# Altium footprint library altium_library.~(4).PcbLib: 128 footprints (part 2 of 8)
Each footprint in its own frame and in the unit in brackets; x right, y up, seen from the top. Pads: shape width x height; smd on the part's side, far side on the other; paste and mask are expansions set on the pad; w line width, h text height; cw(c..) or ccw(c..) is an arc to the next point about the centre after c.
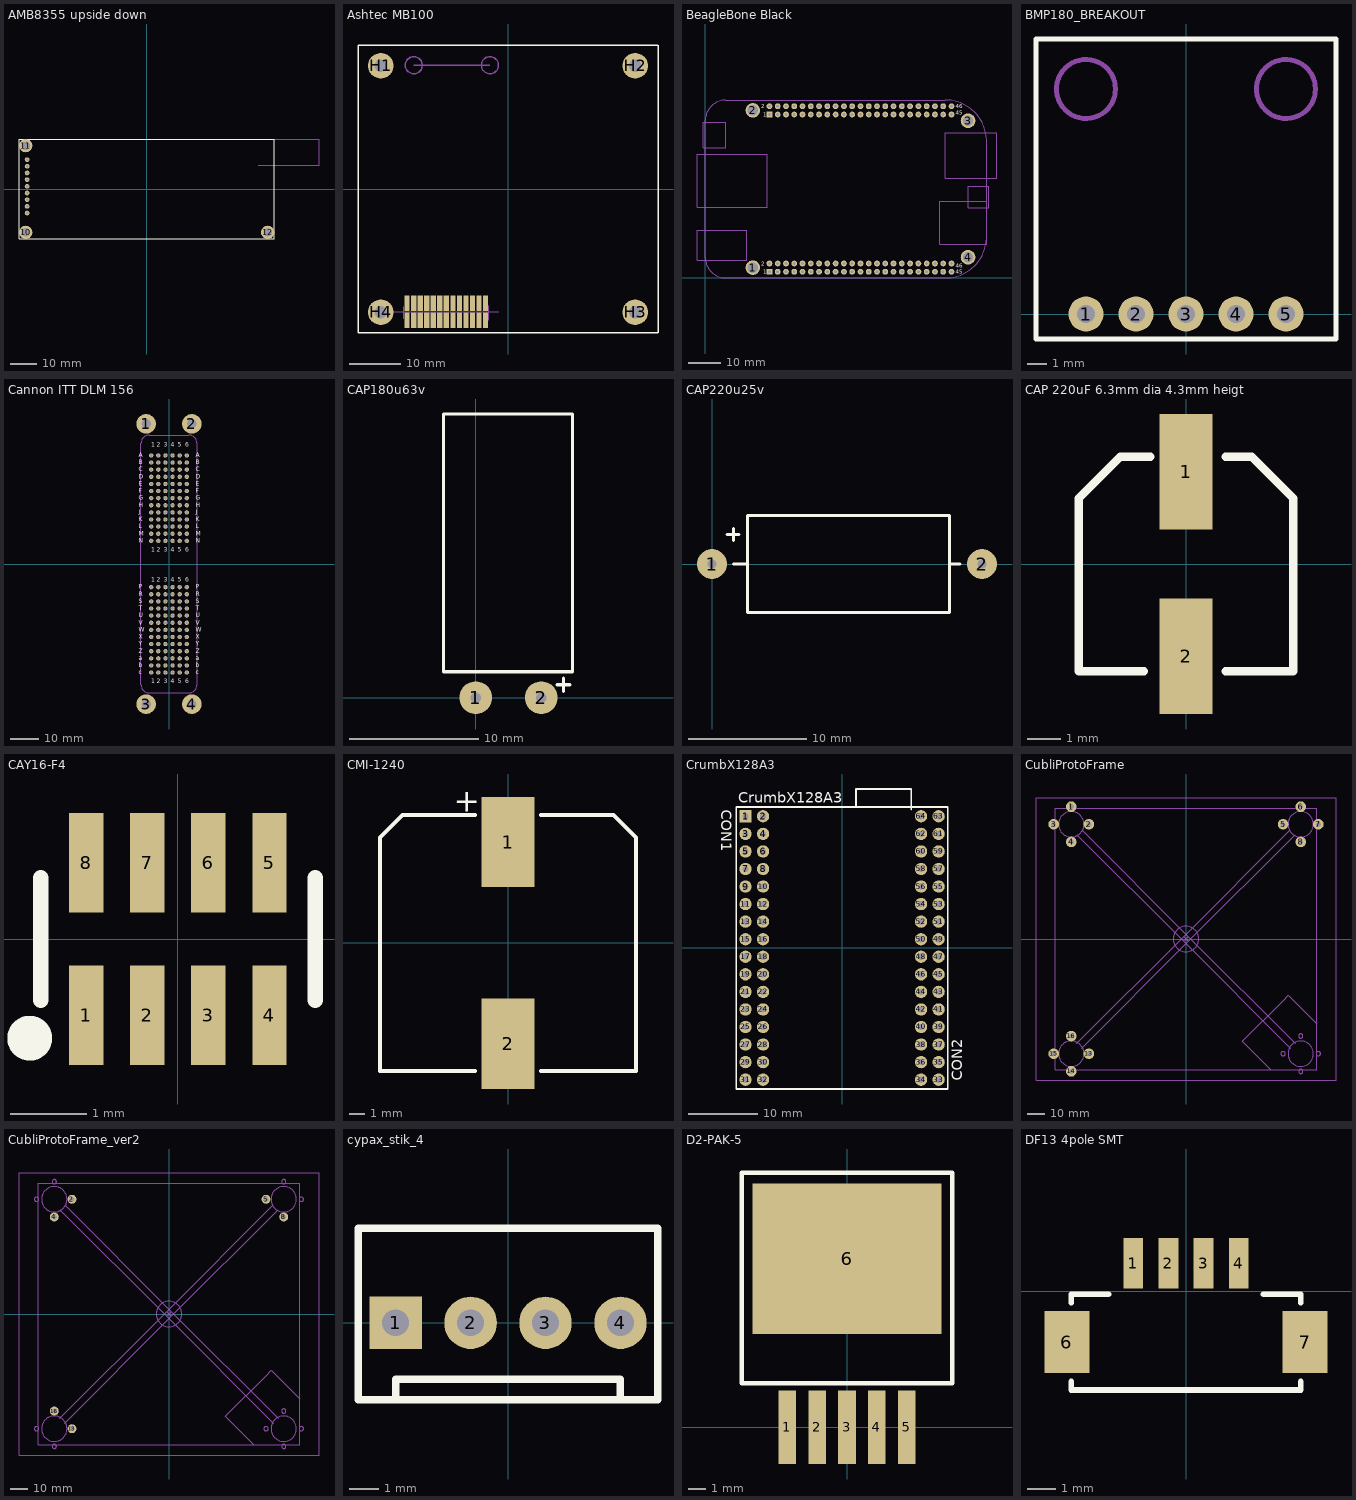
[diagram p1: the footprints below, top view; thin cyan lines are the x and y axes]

## AMB8355 upside down [mil] "Amber Wireless 868Mhz -- RTK GPS"
pads (12):
  round 70 hole 35.43: 1(-1790.16,440) 2(-1790.16,340) 3(-1790.16,240) 4(-1790.16,140) 5(-1790.16,40) 6(-1790.16,-60) 7(-1790.16,-160) 8(-1790.16,-260) 9(-1790.16,-360)
  round 200 hole 125.98: 10(-1811.02,-649.61) 11(-1811.02,649.61) 12(1811.02,-649.61)
Top Overlay:
  lines w10: -1909.45,-748.03 -1909.45,748.03 1909.45,748.03 1909.45,-748.03 -1909.45,-748.03
Mechanical 1:
  lines w10: 1673.23,354.33 2578.74,354.33 2578.74,748.03 1909.45,748.03

## Ashtec MB100 [mm] "RTK GPS reciever"
pads (30):
  rect 1x3 smd: 1(-19.634,-22.225) 2(-19.634,-25.578) 3(-18.364,-22.225) 4(-18.364,-25.578) 5(-17.094,-22.225) 6(-17.094,-25.578) 7(-15.824,-22.225) 8(-15.824,-25.578) 9(-14.554,-22.225) 10(-14.554,-25.578) 11(-13.284,-22.225) 12(-13.284,-25.578) 13(-12.014,-22.225) 14(-12.014,-25.578) 15(-10.744,-22.225) 16(-10.744,-25.578) 17(-9.474,-22.225) 18(-9.474,-25.578) 19(-8.204,-22.225) 20(-8.204,-25.578) 21(-6.934,-22.225) 22(-6.934,-25.578) 23(-5.664,-22.225) 24(-5.664,-25.578) 25(-4.394,-22.225) 26(-4.394,-25.578)
  round 5 hole 2.4: H1(-24.765,24) H2(24.765,24) H3(24.765,-24) H4(-24.765,-24)
Top Overlay:
  lines w0.254: -29.21,-28 -29.21,28 ; -29.2,-28 29.2,-28 ; -29.2,28 29.2,28 ; 29.21,-28 29.21,28
Mechanical 1:
  circle w0.254: c-3.52,24.1 r1.663
  circle w0.254: c-18.37,24.1 r1.663
  lines w0.025: -24.765,-23.9 -1.8,-23.9 ; -20.26,-25.298 -20.26,-22.898 ; -3.76,-25.598 -3.76,-22.698
  lines w0.254: -18.37,24.1 -3.52,24.1

## BeagleBone Black [mil]
pads (96):
  round 177.16 hole 125.98: 1(575,125) 2(575,2025) 3(3175,1900) 4(3175,250)
  rect 70x70 hole 35.43: P8-1(775,1975) P9-1(775,75)
  round 70 hole 35.43: P8-2(775,2075) P8-3(875,1975) P8-4(875,2075) P8-5(975,1975) P8-6(975,2075) P8-7(1075,1975) P8-8(1075,2075) P8-9(1175,1975) P8-10(1175,2075) P8-11(1275,1975) P8-12(1275,2075) P8-13(1375,1975) P8-14(1375,2075) P8-15(1475,1975) P8-16(1475,2075) P8-17(1575,1975) P8-18(1575,2075) P8-19(1675,1975) P8-20(1675,2075) P8-21(1775,1975) P8-22(1775,2075) P8-23(1875,1975) P8-24(1875,2075) P8-25(1975,1975) P8-26(1975,2075) P8-27(2075,1975) P8-28(2075,2075) P8-29(2175,1975) P8-30(2175,2075) P8-31(2275,1975) P8-32(2275,2075) P8-33(2375,1975) P8-34(2375,2075) P8-35(2475,1975) P8-36(2475,2075) P8-37(2575,1975) P8-38(2575,2075) P8-39(2675,1975) P8-40(2675,2075) P8-41(2775,1975) P8-42(2775,2075) P8-43(2875,1975) P8-44(2875,2075) P8-45(2975,1975) P8-46(2975,2075) P9-2(775,175) P9-3(875,75) P9-4(875,175) P9-5(975,75) P9-6(975,175) P9-7(1075,75) P9-8(1075,175) P9-9(1175,75) P9-10(1175,175) P9-11(1275,75) P9-12(1275,175) P9-13(1375,75) P9-14(1375,175) P9-15(1475,75) P9-16(1475,175) P9-17(1575,75) P9-18(1575,175) P9-19(1675,75) P9-20(1675,175) P9-21(1775,75) P9-22(1775,175) P9-23(1875,75) P9-24(1875,175) P9-25(1975,75) P9-26(1975,175) P9-27(2075,75) P9-28(2075,175) P9-29(2175,75) P9-30(2175,175) P9-31(2275,75) P9-32(2275,175) P9-33(2375,75) P9-34(2375,175) P9-35(2475,75) P9-36(2475,175) P9-37(2575,75) P9-38(2575,175) P9-39(2675,75) P9-40(2675,175) P9-41(2775,75) P9-42(2775,175) P9-43(2875,75) P9-44(2875,175) P9-45(2975,75) P9-46(2975,175)
Top Overlay:
  text "1" at 700,1950 h50
  text "2" at 675,2050 h50
  text "45" at 3025,1975 h50
  text "46" at 3025,2050 h50
  text "46" at 3025,125 h50
  text "45" at 3025,50 h50
  text "2" at 675,150 h50
  text "1" at 700,50 h50
Bottom Overlay:
  text "1" at 700,1950 h50
  text "2" at 725,2050 h50
  text "45" at 3125,1975 h50
  text "46" at 3125,2050 h50
  text "46" at 3125,125 h50
  text "45" at 3125,50 h50
  text "2" at 725,150 h50
  text "1" at 700,50 h50
Mechanical 1:
  lines w10: 0,250 ccw(c250,250) 250,0 2900,0 ccw(c2900,500) 3400,500 3400,1650 ccw(c2900,1650) 2900,2150 250,2150 ccw(c250,1900) 0,1900 0,250
Mechanical 2:
  lines w10: -100,215 500,215 500,575 -100,575 -100,215 ; -100,855 750,855 750,1495 -100,1495 -100,855 ; -25,1575 250,1575 250,1880 -25,1880 -25,1575 ; 2834.65,405 2834.65,925 3400,925 3400,405 2834.65,405 ; 2900,1205 2900,1755 3525,1755 3525,1205 2900,1205 ; 3175,850 3425,850 3425,1110 3175,1110 3175,850

## BMP180_BREAKOUT [mil]
pads (5):
  round 70 hole 35.43: 1(-200,0) 2(-100,0) 3(0,0) 4(100,0) 5(200,0)
Top Overlay:
  lines w10: -300,-50 300,-50 300,550 -300,550 -300,-50
Mechanical 1:
  circle w10: c200,450 r59.06
  circle w10: c-200,450 r59.06

## Cannon ITT DLM 156 [mil] "Cannon ITT ZIF DLM 156 pin Connector"
pads (160):
  round 275.59 hole 129.92: 1(-320.08,1968.9) 2(320.08,1968.9) 3(-320.08,-1968.9) 4(320.08,-1968.9)
  round 60 hole 39.37: A1(-250,1525) A2(-150,1525) A3(-50,1525) A4(50,1525) A5(150,1525) A6(250,1525) a¤1(-250,-1325) a¤2(-150,-1325) a¤3(-50,-1325) a¤4(50,-1325) a¤5(150,-1325) a¤6(250,-1325) B1(-250,1425) B2(-150,1425) B3(-50,1425) B4(50,1425) B5(150,1425) B6(250,1425) b¤1(-250,-1425) b¤2(-150,-1425) b¤3(-50,-1425) b¤4(50,-1425) b¤5(150,-1425) b¤6(250,-1425) C1(-250,1325) C2(-150,1325) C3(-50,1325) C4(50,1325) C5(150,1325) C6(250,1325) c¤1(-250,-1525) c¤2(-150,-1525) c¤3(-50,-1525) c¤4(50,-1525) c¤5(150,-1525) c¤6(250,-1525) D1(-250,1225) D2(-150,1225) D3(-50,1225) D4(50,1225) D5(150,1225) D6(250,1225) E1(-250,1125) E2(-150,1125) E3(-50,1125) E4(50,1125) E5(150,1125) E6(250,1125) F1(-250,1025) F2(-150,1025) F3(-50,1025) F4(50,1025) F5(150,1025) F6(250,1025) G1(-250,925) G2(-150,925) G3(-50,925) G4(50,925) G5(150,925) G6(250,925) H1(-250,825) H2(-150,825) H3(-50,825) H4(50,825) H5(150,825) H6(250,825) J1(-250,725) J2(-150,725) J3(-50,725) J4(50,725) J5(150,725) J6(250,725) K1(-250,625) K2(-150,625) K3(-50,625) K4(50,625) K5(150,625) K6(250,625) L1(-250,525) L2(-150,525) L3(-50,525) L4(50,525) L5(150,525) L6(250,525) M1(-250,425) M2(-150,425) M3(-50,425) M4(50,425) M5(150,425) M6(250,425) N1(-250,325) N2(-150,325) N3(-50,325) N4(50,325) N5(150,325) N6(250,325) P1(-250,-325) P2(-150,-325) P3(-50,-325) P4(50,-325) P5(150,-325) P6(250,-325) R1(-250,-425) R2(-150,-425) R3(-50,-425) R4(50,-425) R5(150,-425) R6(250,-425) S1(-250,-525) S2(-150,-525) S3(-50,-525) S4(50,-525) S5(150,-525) S6(250,-525) T1(-250,-625) T2(-150,-625) T3(-50,-625) T4(50,-625) T5(150,-625) T6(250,-625) U1(-250,-725) U2(-150,-725) U3(-50,-725) U4(50,-725) U5(150,-725) U6(250,-725) V1(-250,-825) V2(-150,-825) V3(-50,-825) V4(50,-825) V5(150,-825) V6(250,-825) W1(-250,-925) W2(-150,-925) W3(-50,-925) W4(50,-925) W5(150,-925) W6(250,-925) X1(-250,-1025) X2(-150,-1025) X3(-50,-1025) X4(50,-1025) X5(150,-1025) X6(250,-1025) Y1(-250,-1125) Y2(-150,-1125) Y3(-50,-1125) Y4(50,-1125) Y5(150,-1125) Y6(250,-1125) Z1(-250,-1225) Z2(-150,-1225) Z3(-50,-1225) Z4(50,-1225) Z5(150,-1225) Z6(250,-1225)
Top Overlay:
  text "1" at -250,-1675 h60
  text "2" at -175,-1675 h60
  text "3" at -75,-1675 h60
  text "4" at 25,-1675 h60
  text "5" at 125,-1675 h60
  text "6" at 225,-1675 h60
  text "1" at -250,-250 h60
  text "2" at -175,-250 h60
  text "3" at -75,-250 h60
  text "4" at 25,-250 h60
  text "5" at 125,-250 h60
  text "6" at 225,-250 h60
  text "1" at -250,175 h60
  text "2" at -175,175 h60
  text "3" at -75,175 h60
  text "4" at 25,175 h60
  text "5" at 125,175 h60
  text "6" at 225,175 h60
  text "6" at 225,1650 h60
  text "5" at 125,1650 h60
  text "4" at 25,1650 h60
  text "3" at -75,1650 h60
  text "2" at -175,1650 h60
  text "1" at -250,1650 h60
  text "A" at 375,1500 h60
  text "B" at 375,1400 h60
  text "C" at 375,1300 h60
  text "D" at 375,1200 h60
  text "E" at 375,1100 h60
  text "F" at 375,1000 h60
  text "G" at 375,900 h60
  text "H" at 375,800 h60
  text "J" at 375,700 h60
  text "K" at 375,600 h60
  text "L" at 375,500 h60
  text "M" at 375,400 h60
  text "N" at 375,300 h60
  text "P" at 375,-350 h60
  text "R" at 375,-450 h60
  text "S" at 375,-550 h60
  text "T" at 375,-650 h60
  text "U" at 375,-750 h60
  text "V" at 375,-850 h60
  text "W" at 375,-950 h60
  text "X" at 375,-1050 h60
  text "Y" at 375,-1150 h60
  text "Z" at 375,-1250 h60
  text "a" at 375,-1350 h60
  text "b" at 375,-1450 h60
  text "c" at 375,-1550 h60
  text "c" at -425,-1550 h60
  text "b" at -425,-1450 h60
  text "a" at -425,-1350 h60
  text "Z" at -425,-1250 h60
  text "Y" at -425,-1150 h60
  text "X" at -425,-1050 h60
  text "W" at -425,-950 h60
  text "V" at -425,-850 h60
  text "U" at -425,-750 h60
  text "T" at -425,-650 h60
  text "S" at -425,-550 h60
  text "R" at -425,-450 h60
  text "P" at -425,-350 h60
  text "N" at -425,300 h60
  text "M" at -425,400 h60
  text "L" at -425,500 h60
  text "K" at -425,600 h60
  text "J" at -425,700 h60
  text "H" at -425,800 h60
  text "G" at -425,900 h60
  text "F" at -425,1000 h60
  text "E" at -425,1100 h60
  text "D" at -425,1200 h60
  text "C" at -425,1300 h60
  text "B" at -425,1400 h60
  text "A" at -425,1500 h60
Bottom Overlay:
  text "6" at 275,-1675 h60
  text "5" at 175,-1675 h60
  text "4" at 75,-1675 h60
  text "3" at -25,-1675 h60
  text "2" at -125,-1675 h60
  text "1" at -225,-1675 h60
  text "6" at 275,-250 h60
  text "5" at 175,-250 h60
  text "4" at 75,-250 h60
  text "3" at -25,-250 h60
  text "2" at -125,-250 h60
  text "1" at -225,-250 h60
  text "6" at 275,175 h60
  text "5" at 175,175 h60
  text "4" at 75,175 h60
  text "3" at -25,175 h60
  text "2" at -125,175 h60
  text "1" at -225,175 h60
  text "1" at -225,1650 h60
  text "2" at -125,1650 h60
  text "3" at -25,1650 h60
  text "4" at 75,1650 h60
  text "5" at 175,1650 h60
  text "6" at 275,1650 h60
  text "A" at -375,1500 h60
  text "B" at -375,1400 h60
  text "C" at -375,1300 h60
  text "D" at -375,1200 h60
  text "E" at -375,1100 h60
  text "F" at -375,1000 h60
  text "G" at -375,900 h60
  text "H" at -375,800 h60
  text "J" at -375,700 h60
  text "K" at -375,600 h60
  text "L" at -375,500 h60
  text "M" at -375,400 h60
  text "N" at -375,300 h60
  text "P" at -375,-350 h60
  text "R" at -375,-450 h60
  text "S" at -375,-550 h60
  text "T" at -375,-650 h60
  text "U" at -375,-750 h60
  text "V" at -375,-850 h60
  text "W" at -375,-950 h60
  text "X" at -375,-1050 h60
  text "Y" at -375,-1150 h60
  text "Z" at -375,-1250 h60
  text "a" at -375,-1350 h60
  text "b" at -375,-1450 h60
  text "c" at -375,-1550 h60
  text "c" at 425,-1550 h60
  text "b" at 425,-1450 h60
  text "a" at 425,-1350 h60
  text "Z" at 425,-1250 h60
  text "Y" at 425,-1150 h60
  text "X" at 425,-1050 h60
  text "W" at 425,-950 h60
  text "V" at 425,-850 h60
  text "U" at 425,-750 h60
  text "T" at 425,-650 h60
  text "S" at 425,-550 h60
  text "R" at 425,-450 h60
  text "P" at 425,-350 h60
  text "N" at 425,300 h60
  text "M" at 425,400 h60
  text "L" at 425,500 h60
  text "K" at 425,600 h60
  text "J" at 425,700 h60
  text "H" at 425,800 h60
  text "G" at 425,900 h60
  text "F" at 425,1000 h60
  text "E" at 425,1100 h60
  text "D" at 425,1200 h60
  text "C" at 425,1300 h60
  text "B" at 425,1400 h60
  text "A" at 425,1500 h60
Mechanical 1:
  lines w10: -393.7,-1692.91 ccw(c-275.59,-1692.91) -275.59,-1811.02 275.59,-1811.02 ccw(c275.59,-1692.91) 393.7,-1692.91 393.7,1692.91 ccw(c275.59,1692.91) 275.59,1811.02 -275.59,1811.02 ccw(c-275.59,1692.91) -393.7,1692.91 -393.7,-1692.91

## CAP180u63v [mm]
pads (2):
  round 2.54 hole 0.8: 1(0,0) 2(5.08,0)
Top Overlay:
  lines w0.254: 6.3,1 7.316,1 ; 6.81,0.492 6.81,1.508 ; -2.5,2 7.5,2 7.5,22 -2.5,22 -2.5,2

## CAP220u25v [mm]
pads (2):
  round 2.54 hole 0.8: 1(0,0) 2(22.86,0)
Top Overlay:
  lines w0.254: 1.284,2.5 2.3,2.5 ; 1.8,0 3,0 3,4.1 20.1,4.1 20.1,-4.1 3,-4.1 3,-1.045 3,0.3 ; 1.8,2 1.8,3.016 ; 20.1,0 21,0

## CAP 220uF 6.3mm dia 4.3mm heigt [mm]
height 4.3
pads (2):
  rect 1.6x3.5 smd: 1(0,2.8) 2(0,-2.8)
Top Overlay:
  lines w0.254: -1.275,-3.25 -3.25,-3.25 -3.25,2 -2,3.25 -1.075,3.25 ; 1.2,-3.25 3.25,-3.25 3.25,2 2,3.25 1.2,3.25
3D body: height 4.21, standoff 0, extent -3.25,-3.6 3.25,3.6

## CAY16-F4 [mm] "4 x resistor network  1206size"
pads (8):
  rect 0.45x1.3 smd: 1(-1.2,-1) 2(-0.4,-1) 3(0.4,-1) 4(1.2,-1) 5(1.2,1) 6(0.4,1) 7(-0.4,1) 8(-1.2,1)
Top Overlay:
  circle w0.305: c-1.941,-1.3 r0.141
  lines w0.203: -1.8,-0.8 -1.8,0.8 ; 1.8,-0.8 1.8,0.8
3D body: height 0.5, standoff 0, extent -1.6,-0.8 1.6,0.8

## CMI-1240 [mm] "Buzzer CMI-1240"
height 8
pads (2):
  rect 3.5x6 smd: 1(0,6.7) 2(0,-6.7)
Top Overlay:
  lines w0.254: -2.2,-8.5 -8.5,-8.5 -8.5,7 -7,8.5 -2.2,8.5 ; 2.2,-8.5 8.5,-8.5 8.5,-4.7 8.5,7 7,8.5 2.2,8.5
  text "+" at -3.6,8.7 h1.52

## CrumbX128A3 [mil]
pads (64):
  rect 70x70 hole 35.43: 1(-550,750)
  round 70 hole 35.43: 2(-450,750) 3(-550,650) 4(-450,650) 5(-550,550) 6(-450,550) 7(-550,450) 8(-450,450) 9(-550,350) 10(-450,350) 11(-550,250) 12(-450,250) 13(-550,150) 14(-450,150) 15(-550,50) 16(-450,50) 17(-550,-50) 18(-450,-50) 19(-550,-150) 20(-450,-150) 21(-550,-250) 22(-450,-250) 23(-550,-350) 24(-450,-350) 25(-550,-450) 26(-450,-450) 27(-550,-550) 28(-450,-550) 29(-550,-650) 30(-450,-650) 31(-550,-750) 32(-450,-750) 33(550,-750) 34(450,-750) 35(550,-650) 36(450,-650) 37(550,-550) 38(450,-550) 39(550,-450) 40(450,-450) 41(550,-350) 42(450,-350) 43(550,-250) 44(450,-250) 45(550,-150) 46(450,-150) 47(550,-50) 48(450,-50) 49(550,50) 50(450,50) 51(550,150) 52(450,150) 53(550,250) 54(450,250) 55(550,350) 56(450,350) 57(550,450) 58(450,450) 59(550,550) 60(450,550) 61(550,650) 62(450,650) 63(550,750) 64(450,750)
Top Overlay:
  lines w10: 78.74,803.15 78.74,905.51 393.7,905.51 393.7,787.4 ; -602.36,-803.15 602.36,-803.15 602.36,803.15 -602.36,803.15 -602.36,-803.15
  text "CrumbX128A3" at -590.55,826.77 h60
  text "." at 633.86,-787.4 h60
  text "CON2" at 685.04,-755.91 h60
  text "CON1" at -688.98,787.4 h60

## CubliProtoFrame [mm]
pads (12):
  round 6 hole 2.8: 1(-65,75) 2(-55,65) 3(-75,65) 4(-65,55) 5(55,65) 6(65,75) 7(75,65) 8(65,55) 13(-55,-65) 14(-65,-75) 15(-75,-65) 16(-65,-55)
Mechanical 3:
  lines w0.254: -62,59.172 -1.414,-1.414 ; -61.828,-59 -1.414,1.414 ; -59.172,-62 1.414,-1.414 ; -59.172,62 1.414,1.414 ; 59,61.828 -1.414,1.414 ; 59.086,-61.914 -1.414,-1.414 ; 61.828,-59 1.414,1.414 ; 61.828,59 1.414,-1.414 ; -1.414,-1.414 0,0 ; -1.414,1.414 0,0 ; 0,0 1.414,1.414 ; 0,0 1.414,-1.414
Mechanical 5:
  circle w0.254: c-55,-65 r1.25
  circle w0.254: c-65,-75 r1.25
  circle w0.254: c-75,-65 r1.25
  circle w0.254: c-65,-55 r1.25
  circle w0.254: c-65,55 r1.25
  circle w0.254: c-75,65 r1.25
  circle w0.254: c-65,75 r1.25
  circle w0.254: c-55,65 r1.25
  circle w0.254: c55,65 r1.25
  circle w0.254: c65,75 r1.25
  circle w0.254: c75,65 r1.25
  circle w0.254: c65,55 r1.25
  circle w0.254: c75,-65 r1.25
  circle w0.254: c55,-65 r1.25
  circle w0.254: c65,-75 r1.25
  circle w0.254: c65,-55 r1.25
  circle w0.254: c65,-65 r7.2
  circle w0.254: c-65,-65 r7.2
  circle w0.254: c65,65 r7.2
  circle w0.254: c-65,65 r7.2
  circle w0.254: c0,0 r7.2
  lines w0.254: 48,-74 32,-58 55,-35 58,-32 74,-48 ; -85,-80 85,-80 85,80 -85,80 -85,-80 ; -74,-74 74,-74 74,74 -74,74 -74,-74

## CubliProtoFrame_ver2 [mm] "med yderste huller fra  og mindre pad"
pads (6):
  round 5.08 hole 2.8: 2(-55,65) 4(-65,55) 5(55,65) 8(65,55) 13(-55,-65) 16(-65,-55)
Mechanical 3:
  lines w0.254: -62,59.172 -1.414,-1.414 ; -61.828,-59 -1.414,1.414 ; -59.172,-62 1.414,-1.414 ; -59.172,62 1.414,1.414 ; 59,61.828 -1.414,1.414 ; 59.086,-61.914 -1.414,-1.414 ; 61.828,-59 1.414,1.414 ; 61.828,59 1.414,-1.414 ; -1.414,-1.414 0,0 ; -1.414,1.414 0,0 ; 0,0 1.414,1.414 ; 0,0 1.414,-1.414
Mechanical 5:
  circle w0.254: c-55,-65 r1.25
  circle w0.254: c-65,-75 r1.25
  circle w0.254: c-75,-65 r1.25
  circle w0.254: c-65,-55 r1.25
  circle w0.254: c-65,55 r1.25
  circle w0.254: c-75,65 r1.25
  circle w0.254: c-65,75 r1.25
  circle w0.254: c-55,65 r1.25
  circle w0.254: c55,65 r1.25
  circle w0.254: c65,75 r1.25
  circle w0.254: c75,65 r1.25
  circle w0.254: c65,55 r1.25
  circle w0.254: c75,-65 r1.25
  circle w0.254: c55,-65 r1.25
  circle w0.254: c65,-75 r1.25
  circle w0.254: c65,-55 r1.25
  circle w0.254: c65,-65 r7.2
  circle w0.254: c-65,-65 r7.2
  circle w0.254: c65,65 r7.2
  circle w0.254: c-65,65 r7.2
  circle w0.254: c0,0 r7.2
  lines w0.254: 48,-74 32,-58 55,-35 58,-32 74,-48 ; -85,-80 85,-80 85,80 -85,80 -85,-80 ; -74,-74 74,-74 74,74 -74,74 -74,-74

## cypax_stik_4 [mil]
pads (4):
  rect 70x70 hole 35.43: 1(-150,0)
  round 70 hole 35.43: 2(-50,0) 3(50,0) 4(150,0)
Top Overlay:
  lines w10: -150,-100 -150,-75 150,-75 150,-100 ; -200,-102.36 -200,125.98 200,125.98 200,-102.36 -200,-102.36

## D2-PAK-5 [mm]
pads (6):
  rect 1x4.2 smd: 1(-3.4,0) 2(-1.7,0) 3(0,0) 4(1.7,0) 5(3.4,0)
  rect 10.8x8.6 smd: 6(0,9.6)
Top Overlay:
  lines w0.254: -6,2.5 6,2.5 6,14.5 -6,14.5 -6,2.5
  text "." at -5.7,1.8 h1.27
3D body: height 4.56, standoff 0, extent -5.1,-1.007 5.06,13.007

## DF13 4pole SMT [mm] "DF13-4P-1.25V(50) HIROSE (HRS)"
pads (6):
  rect 0.7x1.8 smd: 1(-1.875,1) 2(-0.625,1) 3(0.625,1) 4(1.875,1)
  rect 1.6x2.2 smd: 6(-4.225,-1.8) 7(4.225,-1.8)
Top Overlay:
  lines w0.203: -4.075,-3.2 -4.075,-3.5 4.075,-3.5 4.075,-3.2 ; -4.075,-0.4 -4.075,-0.1 -2.75,-0.1 ; 2.75,-0.1 4.075,-0.1 4.075,-0.4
